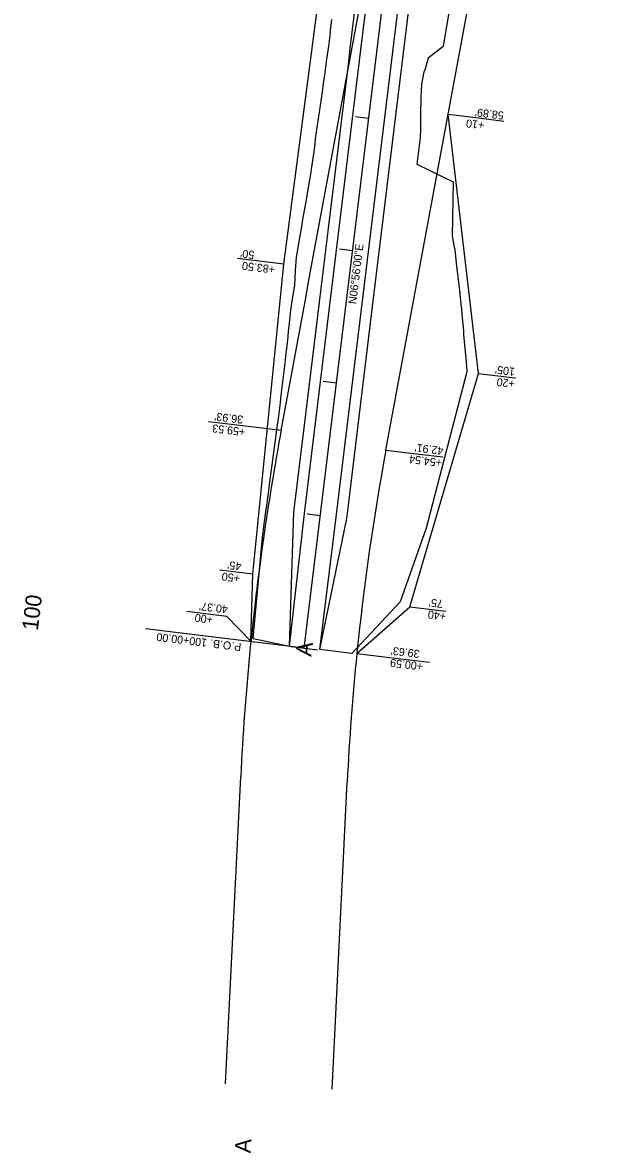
# Model space of a CAD drawing. Extents: x 674098 to 689971, y 764717 to 781049.
# Drawn here: x 688299 to 688740, y 764717 to 765564 of the extents above; entities that cross this region are included whole.
import ezdxf

# ---------------------------------------------------------------- set-up
doc = ezdxf.new("R2010")
doc.units = 0
for name, color, linetype in [('R_Horz Alg', 7, 'Continuous'), ('R_Horz Alg Annot', 7, 'Continuous'), ('R_Horz Alg Station', 7, 'Continuous'), ('R_Horz Alg Station Annot', 7, 'Continuous'), ('R_Proposed Const Limits', 7, 'Continuous'), ('R_Proposed Const Limits Stage 2', 7, 'Continuous'), ('R_Proposed Road', 7, 'Continuous'), ('R_Proposed Road S2', 7, 'Continuous'), ('R_Proposed Shoulder S1', 7, 'Continuous'), ('R_Proposed Shoulder S2', 7, 'Continuous'), ('R_ROW', 7, 'Continuous'), ('R_ROW Annot', 7, 'Continuous'), ('S_EXIST_ROW', 7, 'Continuous'), ('S_EXIST_ROW Annot', 7, 'Continuous')]:
    doc.layers.add(name, color=color, linetype=linetype)

msp = doc.modelspace()

# ---------------------------------------------------------------- linework, layer by layer
at = {"layer": 'R_Horz Alg'}
msp.add_line((688510.61, 765095.41), (688573.4, 765611.83), dxfattribs=at)
at = {"layer": 'R_Horz Alg Station'}
for points in [[(688548.99, 765493.92), (688558.92, 765492.72)], [(688536.92, 765394.65), (688546.85, 765393.45)], [(688524.85, 765295.38), (688534.78, 765294.18)], [(688512.78, 765196.12), (688522.71, 765194.91)], [(688510.61, 765095.41), (688391.49, 765109.9)], [(688500.68, 765096.62), (688520.54, 765094.2)]]:
    msp.add_lwpolyline(points, dxfattribs=at)
at = {"layer": 'R_Proposed Const Limits'}
msp.add_line((688472.14, 765102.66), (688499.6, 765096.98), dxfattribs=at)
msp.add_lwpolyline([(688472.14, 765102.66), (688479.19, 765178.46), (688480.74, 765189.94), (688482.07, 765199.85), (688482.14, 765200.26), (688483.42, 765209.76), (688484.76, 765219.67), (688488.78, 765249.4), (688490.11, 765259.31), (688491.46, 765269.22), (688492.68, 765279.15), (688493.13, 765282.46), (688493.87, 765289.08), (688496.21, 765308.94), (688497.29, 765318.88), (688497.39, 765319.71), (688498.45, 765328.82), (688498.86, 765332.94), (688499.54, 765338.76), (688500.34, 765346.16), (688500.63, 765348.7), (688501.9, 765358.62), (688503.41, 765367.24), (688503.9, 765378.52), (688504.67, 765388.5), (688506.45, 765398.36), (688507.27, 765403.3), (688508.45, 765409.94), (688509.86, 765418.09), (688512.21, 765431.34), (688513.31, 765437.82), (688515, 765447.69), (688515.72, 765452.42), (688516.46, 765457.6), (688518.13, 765467.45), (688518.72, 765473.56), (688519.02, 765477.42), (688520.51, 765487.31), (688521.53, 765493.86), (688522.01, 765497.2), (688523.45, 765507.1), (688524.48, 765514.13), (688524.87, 765517), (688526.2, 765526.92), (688527.52, 765536.83), (688529.13, 765546.71), (688530.15, 765556.66), (688530.31, 765558.21), (688531.17, 765566.61)], dxfattribs=at)
at = {"layer": 'R_Proposed Const Limits Stage 2'}
msp.add_line((688546.37, 765091.29), (688522.17, 765094.24), dxfattribs=at)
msp.add_lwpolyline([(688618.83, 765570.71), (688614.85, 765546.36), (688603.53, 765537.66), (688600.81, 765527.92), (688600.29, 765527.31), (688598.67, 765518.1), (688598.12, 765508.1), (688598, 765505.19), (688597.92, 765498.05), (688597.75, 765487.99), (688597.76, 765484.59), (688597.56, 765477.94), (688596.29, 765468.02), (688595.82, 765464.19), (688595.05, 765458.1), (688622.35, 765444.94), (688622.34, 765444.93), (688621.44, 765404.52), (688623.12, 765395.99), (688623.5, 765394.2), (688624.09, 765389.09), (688624.68, 765383.98), (688625.88, 765373.8), (688627.08, 765363.54), (688628.15, 765353.34), (688628.26, 765352.06), (688629.05, 765343.16), (688629.95, 765332.97), (688630.17, 765330.38), (688630.87, 765322.79), (688631.72, 765312.61), (688632.56, 765303.28), (688632.63, 765302.43), (688602.12, 765185.25), (688582.44, 765130.06), (688546.37, 765091.29)], dxfattribs=at)
at = {"layer": 'R_Proposed Road'}
msp.add_lwpolyline([(688499.6, 765096.98), (688510.82, 765196.35), (688553.07, 765543.79), (688561.52, 765613.28), (688561.57, 765613.69)], dxfattribs=at)
at = {"layer": 'R_Proposed Road S2'}
msp.add_lwpolyline([(688522.17, 765094.24), (688534.59, 765193.47), (688585.28, 765610.38)], dxfattribs=at)
at = {"layer": 'R_Proposed Shoulder S1'}
msp.add_lwpolyline([(688499.6, 765096.98), (688502.87, 765197.32), (688502.87, 765197.31), (688504.08, 765207.24), (688543.91, 765534.83), (688545.12, 765544.76), (688553.57, 765614.24)], dxfattribs=at)
at = {"layer": 'R_Proposed Shoulder S2'}
msp.add_lwpolyline([(688522.17, 765094.24), (688542.53, 765192.51), (688543.73, 765202.44), (688561.86, 765351.53), (688593.26, 765609.41)], dxfattribs=at)
at = {"layer": 'R_ROW'}
for p, q in [((688495.22, 765383.1), (688562.91, 765896.96)), ((688641.42, 765301.36), (688618.59, 765495.53)), ((688589.91, 765126.29), (688641.42, 765301.36)), ((688550.05, 765091.44), (688589.91, 765126.29))]:
    msp.add_line(p, q, dxfattribs=at)
msp.add_lwpolyline([(688470.56, 765100.51), (688472, 765150.71), (688495.22, 765383.1)], dxfattribs=at)
at = {"layer": 'R_ROW Annot'}
for points in [[(688618.59, 765495.53), (688643.4, 765492.52), (688660.42, 765490.45)], [(688495.22, 765383.1), (688460.43, 765387.33)], [(688641.42, 765301.36), (688666.24, 765298.34), (688669.26, 765297.97)], [(688472, 765150.71), (688447.18, 765153.72)], [(688470.56, 765100.51), (688452.38, 765119.14), (688422.59, 765122.76)], [(688589.91, 765126.29), (688614.73, 765123.28), (688616.78, 765123.03)], [(688550.05, 765091.44), (688574.87, 765088.42), (688604.65, 765084.8)]]:
    msp.add_lwpolyline(points, dxfattribs=at)
at = {"layer": 'S_EXIST_ROW'}
for p, q in [((688514.64, 765373.87), (688661.62, 766165.87)), ((688571.89, 765243.87), (688740.27, 766151.28)), ((688511.16, 765355.1), (688514.64, 765373.87)), ((688493.23, 765258.46), (688511.16, 765355.1)), ((688451.5, 764768.84), (688462.88, 764998.95)), ((688539.97, 764938.11), (688542.78, 764995.01)), ((688531.4, 764764.89), (688539.97, 764938.11))]:
    msp.add_line(p, q, dxfattribs=at)
for radius, start, end in [(1949.86, 169.48718, 174.39085), (1869.86, 169.48718, 174.20684), (1949.86, 174.39085, 177.17051), (1869.86, 174.20684, 177.17051)]:
    msp.add_arc((690410.36, 764902.7), radius, start, end, dxfattribs=at)
at = {"layer": 'S_EXIST_ROW Annot'}
for points in [[(688493.23, 765258.46), (688468.41, 765261.48), (688438.63, 765265.1)], [(688571.89, 765243.87), (688596.7, 765240.85), (688614.43, 765238.7)]]:
    msp.add_lwpolyline(points, dxfattribs=at)

# ---------------------------------------------------------------- texts
at = {"layer": 'R_Horz Alg'}
for rotation, p in [(83.06667, (688515.84, 765088.73)), (86.60265, (688470.39, 764716.62))]:
    msp.add_text('A', height=12, rotation=rotation, dxfattribs=at).set_placement(p)
at = {"layer": 'R_Horz Alg Annot'}
msp.add_text('N06%%d56\'00"E', height=6, rotation=83.06667, dxfattribs=at).set_placement((688549.61, 765353.01))
at = {"layer": 'R_Horz Alg Station Annot'}
for s, height, rotation, p in [('100', 12, 83.06667, (688310.68, 765108.1)), ('P.O.B. 100+00.00', 6, 173.06667, (688463.66, 765099.1))]:
    msp.add_text(s, height=height, rotation=rotation, dxfattribs=at).set_placement(p)
at = {"layer": 'R_ROW Annot'}
for s, p in [("58.89'", (688660.56, 765497.45)), ('+10', (688645.92, 765490.17)), ("50'", (688473.4, 765392.99)), ('+83.50', (688488.88, 765382.04)), ("105'", (688668.97, 765305.37)), ('+20', (688668.87, 765296.32)), ("45'", (688463.69, 765159.43)), ('+50', (688462.6, 765150.49)), ("75'", (688614.91, 765131.37)), ("40.37'", (688453.58, 765127.23)), ('+40', (688617.26, 765122.02)), ('+00', (688442.32, 765119.53)), ("39.63'", (688597.43, 765093.84)), ('+00.59', (688599.97, 765084.47))]:
    msp.add_text(s, height=6, rotation=173.06667, dxfattribs=at).set_placement(p)
at = {"layer": 'S_EXIST_ROW Annot'}
for s, p in [("36.93'", (688465.06, 765269.45)), ('+59.53', (688466.6, 765260.19)), ("42.91'", (688615.32, 765246.07)), ('+54.54', (688614.24, 765237.13))]:
    msp.add_text(s, height=6, rotation=173.06667, dxfattribs=at).set_placement(p)

doc.saveas('drawing.dxf')
